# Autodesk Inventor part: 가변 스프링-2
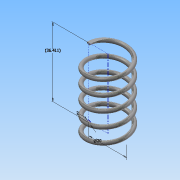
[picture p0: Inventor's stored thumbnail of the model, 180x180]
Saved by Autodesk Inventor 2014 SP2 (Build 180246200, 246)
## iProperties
Created: 2016-01
Part Number: 가변 스프링-2
Material: 스테인레스 스틸
Document SubType Name: Modeling
Designer: Administrator
Density: 8.08 g/cm^3
Appearance: 반연마
Mass: 7.88156 g
Surface Area: 19.7613 cm^2
Volume: 0.975441 cm^3
Author: Administrator
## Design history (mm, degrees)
sketch "스케치2"
  geometry: L1 (0, 0)-(10, 0); L2 (10, 0)-(10, 36.411); L3 (10, 36.411)-(0, 36.411); L4 (0, 36.411)-(0, 0); C1 r 1 at (10, 0)
  constraints: 8 end point, 2 parallel, 1 centre point, 1 coincident, 1 horizontal, 1 perpendicular
  dimensions: "d0" = 2 diameter of C1; "d1" = 20 diameter of L2 L4; "d2" = 36.4112 distance between parallel lines of L3 L1 (derived)
feature "코일1" pitch "d3" = 10; turns "d5" = 5; dims "d4" = 36.4112 (= d2), "d6" = 0, angle "d7" = 90 deg, angle "d8" = 90 deg, "d9" = 0, "d10" = 0
sketch "스케치3"
  geometry: L1 (-11, 0)-(-9, 0) reference; 1 further point
  constraints: 1 horizontal alignment
extrude "돌출1" cut sketch "스케치3" stored distance "d11" = 10; taper "d12" = 0 deg
node "작업 평면1"
sketch "스케치4"
  geometry: L1 (1, 0)-(-1, 0) reference; 1 further point
  constraints: 1 horizontal alignment
extrude "돌출2" cut sketch "스케치4" stored distance "d14" = 10; taper "d15" = 0 deg
node "솔리드1"
node "절단 모서리 투영1"
node "절단 모서리 투영2"
other parameters: "d13" = 0
